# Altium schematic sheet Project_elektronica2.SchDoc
size A4; SheetNumber: 1; SheetTotal: 3
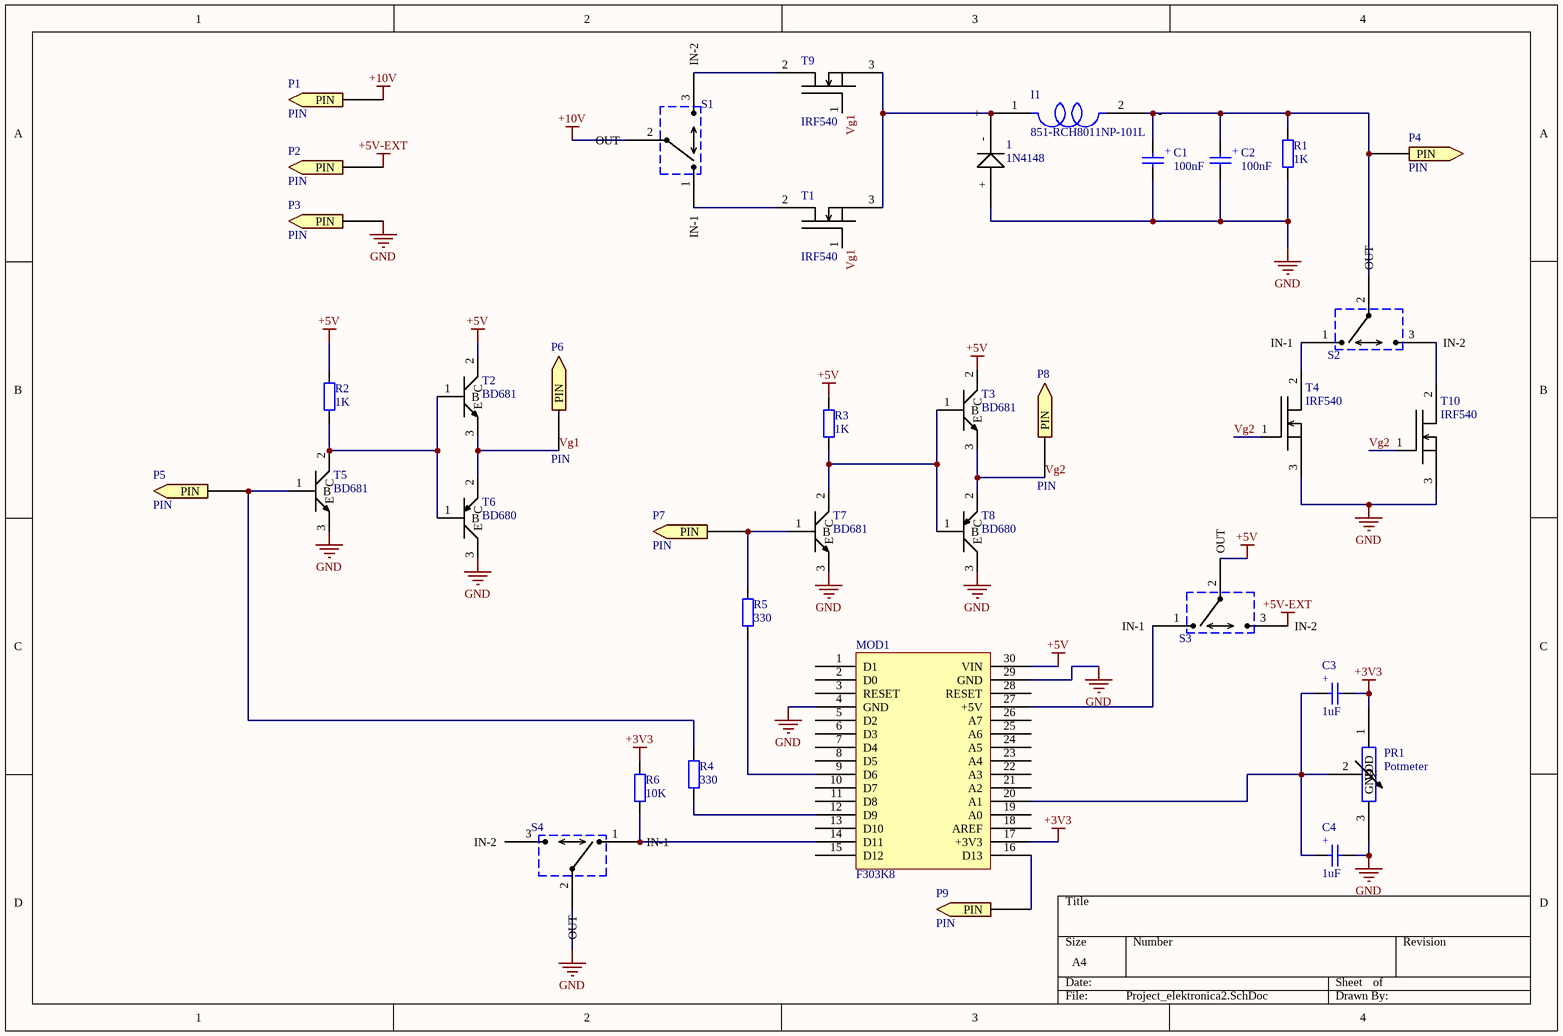
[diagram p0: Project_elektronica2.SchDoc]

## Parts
1  1N4148  [1n4148 [DIODE]]
C1  100nF  [CAP_ELEC_6.3x4.2]
C2  100nF  [CAP_ELEC_6.3x4.2]
C3  1uF  [CAP_ELEC_6.3x4.2]
C4  1uF  [CAP_ELEC_6.3x4.2]
I1  851-RCH8011NP-101L  [Spoel 100uH]
MOD1  F303K8  [F303K8]
P1  PIN  [PIN]
P2  PIN  [PIN]
P3  PIN  [PIN]
P4  PIN  [PIN]
P5  PIN  [Pin]
P6  PIN  [PIN]
P7  PIN  [PIN]
P8  PIN  [PIN]
P9  PIN  [PIN]
PR1  Potmeter  [PM component]
R1  1K  [R1206]
R2  1K  [R1206]
R3  1K  [R1206]
R4  330  [R1206]
R5  330  [R1206]
R6  10K  [R1206]
S1  (no value)  [schakelaar 3-pin]
S2  (no value)  [schakelaar 3-pin]
S3  (no value)  [schakelaar 3-pin]
S4  (no value)  [schakelaar 3-pin]
T1  IRF540  [(MOS)FET]
T2  BD681  [(MOS)FET]
T3  BD681  [(MOS)FET]
T4  IRF540  [(MOS)FET]
T5  BD681  [(MOS)FET]
T6  BD680  [(MOS)FET]
T7  BD681  [(MOS)FET]
T8  BD680  [(MOS)FET]
T9  IRF540  [(MOS)FET]
T10  IRF540  [(MOS)FET]

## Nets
+3V3: C3.2 MOD1.17(+3V3) PR1.1(VDD) R6.2
+5V: MOD1.30(VIN) R2.2 R3.2 S3.2(OUT) T2.2(C) T3.2(C)
+5V-EXT: P2.10(PIN) S3.3(IN-2)
+10V: P1.10(PIN) S1.2(OUT)
GND: 1.+ C1.2 C2.2 C4.2 MOD1.4(GND) MOD1.29(GND) P3.10(PIN) PR1.3(GND) R1.1 S4.2(OUT) T4.3(S) T5.3(E) T6.3(E) T7.3(E) T8.3(E) T10.3(S)
Vg1: P6.10(PIN) T1.1(G) T2.3(E) T6.2(C) T9.1(G)
Vg2: P8.10(PIN) T3.3(E) T4.1(G) T8.2(C) T10.1(G)
Net1_-: 1.- I1.1(+) T1.3(S) T9.3(S)
NetC1_1: C1.1 C2.1 I1.2(-) P4.10(PIN) R1.2 S2.2(OUT)
NetC3_1: C3.1 C4.1 MOD1.20(A1) PR1.2(N)
NetMOD1_9: MOD1.9(D6) R5.2
NetMOD1_12: MOD1.12(D9) R4.1
NetMOD1_14: MOD1.14(D11) R6.1 S4.1(IN-1)
NetMOD1_16: MOD1.16(D13) P9.10(PIN)
NetMOD1_27: MOD1.27(+5V) S3.1(IN-1)
NetP5_10: P5.10(PIN) R4.2 T5.1(B)
NetP7_10: P7.10(PIN) R5.1 T7.1(B)
NetR2_1: R2.1 T2.1(B) T5.2(C) T6.1(B)
NetR3_1: R3.1 T3.1(B) T7.2(C) T8.1(B)
NetS1_1: S1.1(IN-1) T1.2(D)
NetS1_3: S1.3(IN-2) T9.2(D)
NetS2_1: S2.1(IN-1) T4.2(D)
NetS2_3: S2.3(IN-2) T10.2(D)

Not connected (* = marked no-connect by the designer): MOD1 1(D1) 2(D0) 3(RESET) 5(D2) 6(D3) 7(D4) 8(D5) 10(D7) 11(D8) 13(D10) 15(D12) 18(AREF) 19(A0) 21(A2) 22(A3) 23(A4) 24(A5) 25(A6) 26(A7) 28(RESET); S4 3(IN-2)

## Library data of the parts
1 = 1N4148: Diode
C1-C4 = Elco_SMD_6.3mm: Elco SMD 6.3mm
I1 = 851-RCH8011NP-101L: Spoel 100uH
MOD1 = F303K8: Programmable IC
R1-R6 = Resistor_1206: SMD Resistor 1206
S1-S4 = Tuimelschakelaar 3-pin
T1 T4 T9 T10 = IRF540: NPN MOSFET
T2 T3 T5 T7 = BD681: NPN BJT TH
T6 T8 = BD680: PNP BJT TH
